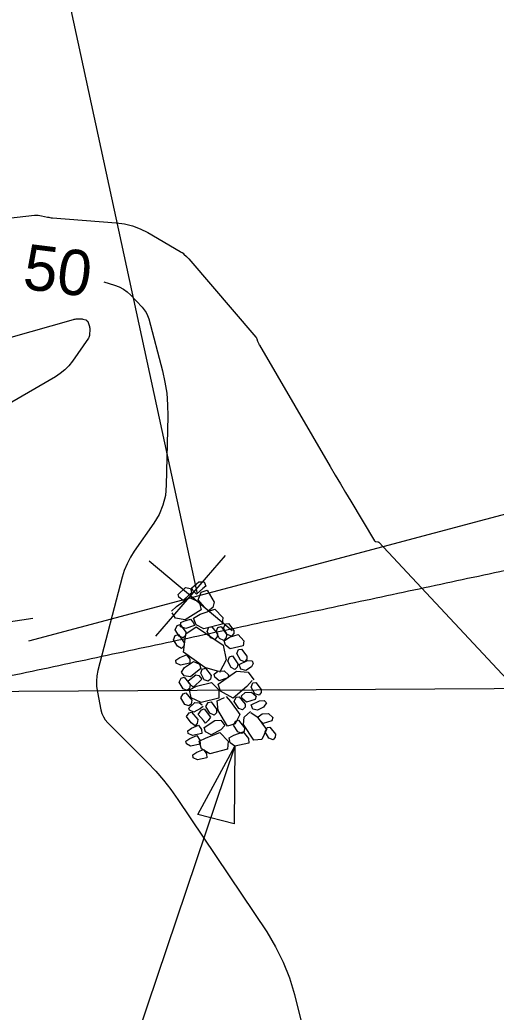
# Model space of a CAD drawing. Extents: x 2384780 to 2405861, y 547869 to 573706.
# Drawn here: x 2390822.9 to 2390854.3, y 552486.8 to 552552.4 of the extents above; entities that cross this region are included whole.
import ezdxf

# ---------------------------------------------------------------- set-up
doc = ezdxf.new("R2010")
doc.units = 0
for name, color, linetype in [('Breaklines', 7, 'Continuous'), ('Old_Level_60', 7, 'Continuous'), ('Old_Level_61', 7, 'Continuous'), ('Old_Level_62', 7, 'Continuous'), ('Old_Level_63', 7, 'Continuous'), ('Sheet Plan CELL', 7, 'Continuous')]:
    doc.layers.add(name, color=color, linetype=linetype)

# ---------------------------------------------------------------- blocks, each defined once
blk = doc.blocks.new('SPOT')
at = {"layer": 'Breaklines'}
for p, q in [((-4.608, -5.326), (4.609, 5.325)), ((-5.48625, 4.61225), (5.48625, -4.61175))]:
    blk.add_line(p, q, dxfattribs=at)

msp = doc.modelspace()

# ---------------------------------------------------------------- linework, layer by layer
at = {"layer": 'Breaklines'}
for p, q in [((2390834.6085, 552514.4455), (2390814.8175, 552606.115)), ((2390837.08025, 552504.376), (2390826.90112, 552474.16879))]:
    msp.add_line(p, q, dxfattribs=at)
for points in [[(2390834.23775, 552514.51375), (2390834.05675, 552514.37925), (2390833.661, 552514.0085), (2390833.385, 552514.22425), (2390833.32975, 552514.4035), (2390833.81825, 552514.855), (2390834.14925, 552514.80025), (2390834.23775, 552514.51375)], [(2390835.16075, 552514.95575), (2390834.97175, 552514.80575), (2390834.54, 552514.424), (2390834.30825, 552514.66625), (2390834.241, 552514.84175), (2390834.70475, 552515.2465), (2390835.06025, 552515.23875), (2390835.16075, 552514.95575)], [(2390832.91, 552513.30575), (2390833.23675, 552513.60275), (2390834.0725, 552514.201), (2390834.72625, 552513.90575), (2390834.849, 552513.381), (2390833.8065, 552512.73225), (2390833.17225, 552512.83725), (2390832.94675, 552513.18625)], [(2390835.338, 552513.32275), (2390835.07025, 552513.554), (2390834.67, 552514.0455), (2390834.86725, 552514.551), (2390835.24575, 552514.681), (2390835.71425, 552513.88375), (2390835.6235, 552513.54175), (2390835.338, 552513.32275)], [(2390834.3625, 552512.8385), (2390834.7915, 552513.10175), (2390835.7515, 552513.42425), (2390836.297, 552512.88625), (2390836.2395, 552512.43675), (2390835.04225, 552512.1195), (2390834.5265, 552512.392), (2390834.3625, 552512.8385)], [(2390833.66525, 552511.53725), (2390833.39875, 552511.63825), (2390833.1355, 552512.067), (2390833.284, 552512.3485), (2390833.46325, 552512.40375), (2390833.8515, 552511.90875), (2390833.82225, 552511.66425), (2390833.66525, 552511.53725)], [(2390833.51, 552512.549), (2390833.72125, 552512.62725), (2390834.1475, 552512.772), (2390834.3555, 552512.52225), (2390834.41075, 552512.343), (2390833.84125, 552512.15425), (2390833.49175, 552512.26875), (2390833.51, 552512.549)], [(2390835.92925, 552509.332), (2390835.10825, 552509.57575), (2390833.69575, 552510.59175), (2390833.84875, 552511.79025), (2390834.5275, 552512.2615), (2390836.31525, 552511.04725), (2390836.5075, 552510.08625), (2390836.0735, 552509.24575)], [(2390835.76625, 552511.42725), (2390835.49975, 552511.528), (2390835.24825, 552511.96075), (2390835.3695, 552512.24675), (2390835.5595, 552512.26625), (2390835.9285, 552511.79125), (2390835.91225, 552511.59), (2390835.76625, 552511.42725)], [(2390836.3535, 552511.347), (2390836.07225, 552511.4955), (2390835.8605, 552511.92725), (2390835.9575, 552512.20575), (2390836.1725, 552512.27225), (2390836.55175, 552511.72225), (2390836.4995, 552511.50975), (2390836.3535, 552511.347)], [(2390836.8625, 552511.648), (2390836.584, 552511.74525), (2390836.3325, 552512.17775), (2390836.4655, 552512.4675), (2390836.65575, 552512.48675), (2390837.01275, 552512.0085), (2390837.0085, 552511.81075), (2390836.8625, 552511.648)], [(2390833.5585, 552510.824), (2390833.301, 552510.98), (2390833.03775, 552511.409), (2390833.1505, 552511.67925), (2390833.3655, 552511.7455), (2390833.741, 552511.2075), (2390833.7045, 552510.98675), (2390833.5585, 552510.824)], [(2390836.385, 552511.3305), (2390836.73025, 552511.568), (2390837.29975, 552511.757), (2390837.678, 552511.33725), (2390837.62675, 552510.9945), (2390836.7805, 552510.8115), (2390836.46975, 552511.05575), (2390836.385, 552511.3305)], [(2390833.1815, 552510.0535), (2390833.44225, 552510.22575), (2390833.8935, 552510.41725), (2390834.1005, 552510.128), (2390834.11825, 552509.85875), (2390833.49075, 552509.73025), (2390833.213, 552509.867), (2390833.1815, 552510.0535)], [(2390837.08625, 552509.44075), (2390836.83975, 552509.561), (2390836.616, 552509.989), (2390836.725, 552510.27125), (2390836.94, 552510.3375), (2390837.28425, 552509.816), (2390837.232, 552509.6035), (2390837.08625, 552509.44075)], [(2390837.72625, 552509.95225), (2390837.456, 552510.06525), (2390837.2045, 552510.49775), (2390837.32925, 552510.77175), (2390837.5195, 552510.79125), (2390837.88475, 552510.3285), (2390837.8685, 552510.127), (2390837.72625, 552509.95225)], [(2390833.5555, 552509.26625), (2390833.76375, 552509.566), (2390834.346, 552509.96825), (2390834.757, 552509.78125), (2390834.8455, 552509.4945), (2390834.165, 552508.94425), (2390833.7395, 552509.00925), (2390833.5555, 552509.26625)], [(2390838.297, 552509.84075), (2390838.17325, 552509.60625), (2390837.816, 552509.36525), (2390837.474, 552509.45575), (2390837.366, 552509.76275), (2390837.9135, 552510.02325), (2390838.22975, 552510.01625), (2390838.297, 552509.84075)], [(2390834.905, 552508.7935), (2390834.73525, 552508.62325), (2390834.332, 552508.27625), (2390834.045, 552508.528), (2390833.99725, 552508.68325), (2390834.50025, 552509.087), (2390834.709, 552509.047), (2390834.905, 552508.7935)], [(2390835.32525, 552508.6615), (2390835.06225, 552508.7505), (2390834.831, 552509.20225), (2390834.932, 552509.469), (2390835.147, 552509.53525), (2390835.52325, 552509.03675), (2390835.48225, 552508.7885), (2390835.32525, 552508.6615)], [(2390835.707, 552509.1195), (2390835.95675, 552509.3275), (2390836.3805, 552509.35375), (2390836.671, 552509.09025), (2390836.619, 552508.87775), (2390836.04925, 552508.689), (2390835.76225, 552508.9405), (2390835.707, 552509.1195)], [(2390838.22825, 552508.7075), (2390837.8675, 552508.3085), (2390836.9685, 552507.53375), (2390836.141, 552508.01075), (2390835.98525, 552508.47275), (2390837.202, 552509.3195), (2390837.964, 552509.267), (2390838.344, 552508.7565)], [(2390833.928, 552508.06), (2390833.66125, 552508.16075), (2390833.398, 552508.58975), (2390833.54675, 552508.871), (2390833.72575, 552508.9265), (2390834.126, 552508.43525), (2390834.085, 552508.187), (2390833.928, 552508.06)], [(2390834.0905, 552508.084), (2390834.559, 552508.3465), (2390835.5485, 552508.5735), (2390836.02425, 552508.0925), (2390836.02375, 552507.54275), (2390834.855, 552507.2605), (2390834.19775, 552507.56775), (2390834.0905, 552508.084)], [(2390838.685, 552507.73675), (2390838.4065, 552507.83375), (2390838.15525, 552508.2665), (2390838.27625, 552508.55225), (2390838.4665, 552508.57175), (2390838.83175, 552508.109), (2390838.82725, 552507.9115), (2390838.685, 552507.73675)], [(2390834.05125, 552507.02525), (2390833.7845, 552507.12625), (2390833.52125, 552507.555), (2390833.67, 552507.8365), (2390833.849, 552507.89175), (2390834.24925, 552507.4005), (2390834.20825, 552507.15225), (2390834.05125, 552507.02525)], [(2390836.50075, 552507.65075), (2390836.79775, 552507.324), (2390837.407, 552506.4525), (2390837.097, 552505.8465), (2390836.59925, 552505.67975), (2390835.974, 552506.7295), (2390835.92475, 552507.35525), (2390836.40425, 552507.58175)], [(2390837.58425, 552506.76875), (2390837.357, 552506.86875), (2390837.03125, 552507.33075), (2390837.17975, 552507.612), (2390837.37, 552507.6315), (2390837.77025, 552507.14025), (2390837.766, 552506.9425), (2390837.58425, 552506.76875)], [(2390837.518, 552507.70325), (2390837.76775, 552507.91125), (2390838.1915, 552507.9375), (2390838.482, 552507.674), (2390838.43, 552507.4615), (2390837.86025, 552507.27275), (2390837.57325, 552507.52425), (2390837.518, 552507.70325)], [(2390834.98775, 552507.0005), (2390834.80675, 552506.86625), (2390834.37425, 552506.61475), (2390834.0965, 552506.7515), (2390834.04025, 552506.891), (2390834.436, 552507.262), (2390834.75575, 552507.243), (2390834.91875, 552507.097)], [(2390835.718, 552506.415), (2390835.42825, 552506.54775), (2390835.177, 552506.9805), (2390835.32575, 552507.26175), (2390835.51225, 552507.29325), (2390835.86925, 552506.81475), (2390835.864, 552506.57775), (2390835.718, 552506.415)], [(2390839.1645, 552507.2435), (2390838.98, 552506.95125), (2390838.58775, 552506.7385), (2390838.27325, 552506.8245), (2390838.173, 552507.1075), (2390838.7205, 552507.36825), (2390839.0255, 552507.397), (2390839.1645, 552507.2435)], [(2390834.45675, 552505.7115), (2390834.18825, 552505.90325), (2390833.90125, 552506.32475), (2390834.06075, 552506.5705), (2390834.228, 552506.622), (2390834.644, 552506.1225), (2390834.60275, 552505.87425), (2390834.45675, 552505.7115)], [(2390835.145, 552505.89775), (2390835.018, 552506.05475), (2390834.67125, 552506.458), (2390834.88775, 552506.7735), (2390835.067, 552506.82875), (2390835.482, 552506.28975), (2390835.32675, 552506.07175), (2390835.145, 552505.89775)], [(2390838.1495, 552506.59), (2390838.56625, 552506.3), (2390839.16425, 552505.4645), (2390838.869, 552504.81075), (2390838.33425, 552504.76325), (2390837.6615, 552505.79825), (2390837.70775, 552506.2835), (2390838.1275, 552506.66175)], [(2390838.6295, 552506.3065), (2390838.883, 552506.5025), (2390839.30675, 552506.52875), (2390839.58525, 552506.2615), (2390839.53325, 552506.04925), (2390838.9635, 552505.86025), (2390838.68475, 552506.1275), (2390838.6295, 552506.3065)], [(2390833.971, 552505.37825), (2390834.22825, 552505.5625), (2390834.67925, 552505.754), (2390834.88625, 552505.46475), (2390834.904, 552505.1955), (2390834.2765, 552505.067), (2390833.99875, 552505.20375), (2390833.971, 552505.37825)], [(2390836.42625, 552505.731), (2390836.15925, 552505.45225), (2390835.519, 552505.1105), (2390835.14375, 552505.30875), (2390835.05525, 552505.5955), (2390835.7615, 552506.062), (2390836.14925, 552506.07725), (2390836.42625, 552505.731)], [(2390837.5415, 552505.212), (2390837.27125, 552505.32475), (2390836.996, 552505.75), (2390837.14475, 552506.03125), (2390837.32375, 552506.0865), (2390837.72775, 552505.58325), (2390837.6985, 552505.33875), (2390837.5415, 552505.212)], [(2390833.85325, 552504.701), (2390834.114, 552504.873), (2390834.565, 552505.06475), (2390834.772, 552504.77525), (2390834.78975, 552504.506), (2390834.16225, 552504.37775), (2390833.8845, 552504.5145), (2390833.85325, 552504.701)], [(2390834.719, 552504.6935), (2390835.18275, 552504.92825), (2390836.0995, 552505.26375), (2390836.6525, 552504.70175), (2390836.59325, 552504.17325), (2390835.432, 552503.867), (2390834.88575, 552504.1955), (2390834.719, 552504.6935)], [(2390836.701, 552504.92625), (2390837.02525, 552505.10475), (2390837.63075, 552505.30475), (2390837.9885, 552504.86575), (2390838.00175, 552504.569), (2390837.08025, 552504.376), (2390836.76475, 552504.5925), (2390836.701, 552504.92625)], [(2390839.608, 552504.79025), (2390839.3295, 552504.8875), (2390839.078, 552505.32), (2390839.211, 552505.60975), (2390839.40125, 552505.62925), (2390839.7665, 552505.16625), (2390839.75025, 552504.965), (2390839.608, 552504.79025)], [(2390834.3035, 552503.79325), (2390834.56425, 552503.9655), (2390835.01525, 552504.157), (2390835.2225, 552503.86775), (2390835.24025, 552503.5985), (2390834.6125, 552503.47025), (2390834.335, 552503.60675), (2390834.3035, 552503.79325)]]:
    msp.add_lwpolyline(points, dxfattribs=at)
msp.add_lwpolyline([(2390834.628, 552499.843), (2390837.08025, 552504.376), (2390837.04975, 552499.22225)], close=True, dxfattribs=at)
at = {"layer": 'Old_Level_60'}
for points in [[(2390821.328, 552539.189), (2390823.84425, 552539.478), (2390823.96425, 552539.48675), (2390824.08375, 552539.48525), (2390824.2025, 552539.47325), (2390824.32075, 552539.451), (2390824.70625, 552539.3615), (2390824.789, 552539.34375), (2390824.87225, 552539.3295), (2390824.95625, 552539.31825), (2390825.0405, 552539.31025), (2390829.234, 552538.99), (2390829.78675, 552538.917), (2390830.321, 552538.784), (2390830.83625, 552538.59075), (2390831.333, 552538.33725), (2390833.48025, 552537.08875), (2390833.5425, 552537.05), (2390833.6025, 552537.00825), (2390833.66025, 552536.96325), (2390833.7155, 552536.91525), (2390833.89225, 552536.7525), (2390833.9295, 552536.71725), (2390833.96575, 552536.68075), (2390834.001, 552536.64325), (2390834.035, 552536.6045), (2390838.48025, 552531.40725), (2390838.49625, 552531.3865), (2390838.51, 552531.36425), (2390838.52125, 552531.341), (2390838.53025, 552531.31625), (2390838.55575, 552531.23325), (2390838.5615, 552531.21575), (2390838.56775, 552531.19825), (2390838.5745, 552531.181), (2390838.58175, 552531.16375), (2390838.64825, 552531.011), (2390838.663, 552530.9785), (2390838.6785, 552530.9465), (2390838.69525, 552530.915), (2390838.71275, 552530.884), (2390843.3825, 552522.874), (2390843.71975, 552522.29725), (2390844.05875, 552521.72125), (2390844.399, 552521.1465), (2390844.741, 552520.5725), (2390846.305, 552517.9545), (2390846.32475, 552517.92875), (2390846.3485, 552517.91), (2390846.3765, 552517.89825), (2390846.4085, 552517.89375), (2390846.52025, 552517.89), (2390846.54325, 552517.88725), (2390846.56425, 552517.88025), (2390846.5835, 552517.869), (2390846.60075, 552517.8535), (2390858.17875, 552505.443)], [(2390800.92075, 552525.365), (2390826.4175, 552532.58625), (2390826.479, 552532.60175), (2390826.54125, 552532.61325), (2390826.604, 552532.621), (2390826.66725, 552532.62525), (2390826.875, 552532.63225), (2390826.91925, 552532.632), (2390826.963, 552532.628), (2390827.0065, 552532.62075), (2390827.0495, 552532.61), (2390827.233, 552532.55575), (2390827.256, 552532.54725), (2390827.2775, 552532.536), (2390827.29725, 552532.522), (2390827.315, 552532.50525), (2390827.371, 552532.446), (2390827.382, 552532.43275), (2390827.39125, 552532.41825), (2390827.3985, 552532.403), (2390827.40375, 552532.38675), (2390827.4725, 552532.127), (2390827.485, 552532.07125), (2390827.49375, 552532.01475), (2390827.4985, 552531.958), (2390827.49925, 552531.90075), (2390827.4925, 552531.586), (2390827.48625, 552531.52025), (2390827.471, 552531.45725), (2390827.44625, 552531.3975), (2390827.41225, 552531.34075), (2390826.36025, 552529.83825), (2390826.12075, 552529.532), (2390825.8525, 552529.25675), (2390825.5555, 552529.01275), (2390825.23, 552528.79975), (2390811.89975, 552521.05825)]]:
    msp.add_lwpolyline(points, dxfattribs=at)
at = {"layer": 'Old_Level_61'}
msp.add_lwpolyline([(2390828.4255, 552535.07025), (2390829.132, 552534.8615), (2390829.4375, 552534.74975), (2390829.7205, 552534.601), (2390829.98075, 552534.41575), (2390830.2185, 552534.1935), (2390830.958, 552533.408), (2390831.10425, 552533.23275), (2390831.22525, 552533.0435), (2390831.32175, 552532.84075), (2390831.393, 552532.624), (2390832.3, 552529.189), (2390832.46775, 552528.44975), (2390832.583, 552527.70425), (2390832.64575, 552526.9525), (2390832.6555, 552526.1945), (2390832.55625, 552521.627), (2390832.4935, 552520.952), (2390832.33575, 552520.308), (2390832.0825, 552519.6955), (2390831.734, 552519.114), (2390830.43975, 552517.2655), (2390830.182, 552516.8605), (2390829.96325, 552516.43725), (2390829.78325, 552515.99625), (2390829.6425, 552515.53725), (2390828.04175, 552509.366), (2390827.9705, 552509.013), (2390827.94, 552508.65875), (2390827.95, 552508.3035), (2390828.00075, 552507.947), (2390828.23225, 552506.78025), (2390828.29825, 552506.539), (2390828.39675, 552506.315), (2390828.528, 552506.1085), (2390828.69175, 552505.9195), (2390831.314, 552503.292), (2390831.861, 552502.71675), (2390832.378, 552502.117), (2390832.86525, 552501.49275), (2390833.3225, 552500.844), (2390839.18625, 552492.08225), (2390839.78025, 552491.10725), (2390840.28375, 552490.092), (2390840.697, 552489.03675), (2390841.0195, 552487.9415), (2390842.148, 552483.40625)], dxfattribs=at)
at = {"layer": 'Old_Level_62'}
msp.add_spline([(2390750.412, 552493.903), (2390756.0595, 552495.08775), (2390761.7115, 552496.27325), (2390767.3675, 552497.4605), (2390773.02325, 552498.648), (2390778.6805, 552499.8365), (2390784.343, 552501.02675), (2390790.009, 552502.21875), (2390795.6745, 552503.412), (2390801.34075, 552504.6065), (2390807.0125, 552505.8035), (2390812.6885, 552507.00325), (2390818.36375, 552508.2045), (2390824.04125, 552509.40825), (2390829.7205, 552510.6145), (2390835.4035, 552511.8235), (2390841.09, 552513.036), (2390846.77575, 552514.25075), (2390852.464, 552515.46875), (2390858.15625, 552516.69075), (2390863.84925, 552517.91575), (2390869.5415, 552519.144), (2390875.24, 552520.37675), (2390880.94175, 552521.614), (2390886.6405, 552522.8545), (2390892.34075, 552524.099), (2390898.047, 552525.34875), (2390903.7545, 552526.60325), (2390909.46275, 552527.86225), (2390915.17275, 552529.12625), (2390920.8815, 552530.39475), (2390926.5955, 552531.669), (2390932.311, 552532.949), (2390938.0255, 552534.23375), (2390943.74275, 552535.5245), (2390949.463, 552536.8215), (2390955.18475, 552538.12475), (2390960.9055, 552539.43375), (2390966.629, 552540.74925), (2390972.35275, 552542.071), (2390978.07775, 552543.3995), (2390983.80575, 552544.73525), (2390989.53425, 552546.078), (2390995.26325, 552547.42775), (2391000.9935, 552548.78475), (2391006.72375, 552550.14925), (2391012.45675, 552551.5215), (2391018.19, 552552.9015), (2391023.92225, 552554.289), (2391029.659, 552555.6855), (2391035.39375, 552557.08975), (2391041.12925, 552558.50225), (2391046.8685, 552559.92425), (2391052.60575, 552561.3545), (2391058.344, 552562.79375), (2391064.082, 552564.24175), (2391069.822, 552565.6995), (2391075.56175, 552567.1665), (2391081.29975, 552568.64275), (2391087.04225, 552570.12925), (2391092.784, 552571.626), (2391098.5215, 552573.1315), (2391104.26275, 552574.648), (2391110.00625, 552576.1755), (2391115.74525, 552577.7125), (2391121.4855, 552579.2605), (2391127.227, 552580.81975), (2391132.9685, 552582.39), (2391138.7075, 552583.97075), (2391144.44775, 552585.56325), (2391150.18875, 552587.168), (2391155.9255, 552588.783), (2391161.6655, 552590.41075), (2391167.4045, 552592.05075), (2391173.043, 552593.674)], degree=3, dxfattribs=at)
at = {"layer": 'Old_Level_63'}
msp.add_lwpolyline([(2390764.70375, 552503.98875), (2390814.9565, 552507.97175), (2390865.9885, 552508.2405), (2390910.967, 552537.3645)], dxfattribs=at)
msp.add_spline([(2390739.62125, 552545.348), (2390745.271, 552546.5335), (2390750.91725, 552547.7185), (2390756.5675, 552548.904), (2390762.221, 552550.09125), (2390767.8725, 552551.2785), (2390773.5255, 552552.467), (2390779.18075, 552553.6565), (2390784.8375, 552554.848), (2390790.49225, 552556.04), (2390796.14925, 552557.234), (2390801.80925, 552558.43025), (2390807.46975, 552559.62825), (2390813.1315, 552560.8285), (2390818.79225, 552562.031), (2390824.45475, 552563.23575), (2390830.117, 552564.443), (2390835.77825, 552565.6525), (2390841.44475, 552566.86575), (2390847.113, 552568.0825), (2390852.7785, 552569.302), (2390858.44025, 552570.5235), (2390864.10825, 552571.7495), (2390869.779, 552572.98025), (2390875.44625, 552574.2135), (2390881.11525, 552575.4515), (2390886.77975, 552576.6925), (2390892.4515, 552577.9385), (2390898.12275, 552579.18975), (2390903.79025, 552580.444), (2390909.46225, 552581.70425), (2390915.13075, 552582.96875), (2390920.80125, 552584.23825), (2390926.47425, 552585.51375), (2390932.143, 552586.794), (2390937.8135, 552588.0795), (2390943.48575, 552589.3715), (2390949.1565, 552590.66875), (2390954.827, 552591.97225), (2390960.5, 552593.28225), (2390966.17, 552594.5985), (2390971.837, 552595.91975), (2390977.51, 552597.24925), (2390983.1815, 552598.5855), (2390988.84775, 552599.9275), (2390994.51775, 552601.27725), (2391000.18725, 552602.6345), (2391005.85475, 552603.9985), (2391011.52375, 552605.37075), (2391017.19125, 552606.7505), (2391022.85825, 552608.138), (2391028.5255, 552609.534), (2391034.19, 552610.9375), (2391039.85525, 552612.34975), (2391045.51975, 552613.7705), (2391051.18175, 552615.1995), (2391056.84525, 552616.63775), (2391062.50425, 552618.08425), (2391068.1655, 552619.54025), (2391073.82775, 552621.0065), (2391079.48125, 552622.48), (2391085.14025, 552623.9645), (2391090.798, 552625.4595), (2391096.44925, 552626.9625), (2391102.10325, 552628.47625), (2391107.75725, 552630.00125), (2391113.40575, 552631.53525), (2391119.05525, 552633.08025), (2391124.703, 552634.636), (2391130.34475, 552636.2015), (2391135.989, 552637.7785), (2391141.63475, 552639.368), (2391147.27575, 552640.968), (2391152.911, 552642.57825), (2391158.5015, 552644.1875)], degree=3, dxfattribs=at)
at = {"layer": 'Sheet Plan CELL'}
for points in [[(2390866.87679, 552522.89166), (2390823.46039, 552511.32303)], [(2390823.7326, 552512.82014), (2390814.2395, 552511.38925), (2390764.5505, 552504.71875)]]:
    msp.add_lwpolyline(points, dxfattribs=at)

# ---------------------------------------------------------------- block references
at = {"layer": 'Old_Level_63', "xscale": 0.5, "yscale": 0.5}
msp.add_blockref('SPOT', (2390834.1705, 552514.3145), dxfattribs=at)

# ---------------------------------------------------------------- texts
at = {"layer": 'Old_Level_61'}
msp.add_text('50', height=3, rotation=352.8521778, dxfattribs=at).set_placement((2390822.9945, 552534.62725))

doc.saveas('drawing.dxf')
